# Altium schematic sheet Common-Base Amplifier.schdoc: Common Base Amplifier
size A4; Organization: Altium Limited; Address1: L3, 12a Rodborough Rd; Address2: Frenchs Forest; Address3: NSW; Address4: Australia 2086; DocumentNumber: 1; SheetNumber: 1; SheetTotal: 1
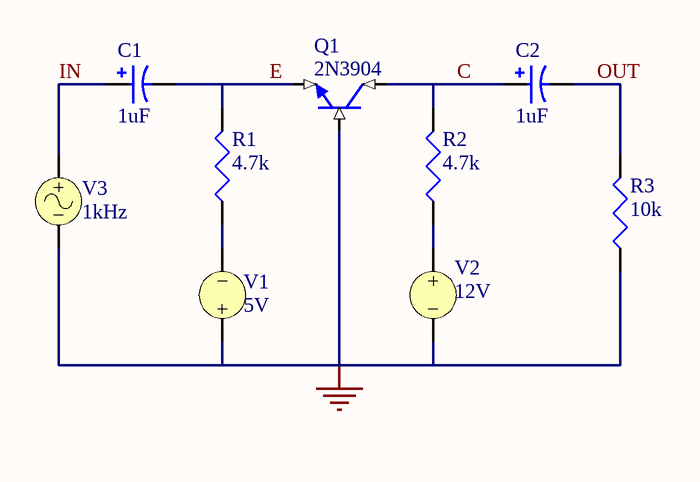
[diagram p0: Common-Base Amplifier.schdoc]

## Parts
C1  1uF
C2  1uF
Q1  2N3904
R1  4.7k
R2  4.7k
R3  10k
V1  5V
V2  12V
V3  1kHz

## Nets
GND: Q1.2(B) R3.2(BOT) V1.1 V2.2 V3.2
C: C2.1 Q1.1(C) R2.1(TOP)
E: C1.2 Q1.3(E) R1.1(TOP)
IN: C1.1 V3.1
OUT: C2.2 R3.1(TOP)
NetR1_2: R1.2(BOT) V1.2
NetR2_2: R2.2(BOT) V2.1

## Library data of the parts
C1 C2 = CAP2: Bi-Polar Capacitor
Q1 = 2N3904: NPN BJT
R1-R3 = RES: Resistor
V1 V2 = VSRC: Voltage Source
V3 = VSIN: Sinusoidal Voltage Source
